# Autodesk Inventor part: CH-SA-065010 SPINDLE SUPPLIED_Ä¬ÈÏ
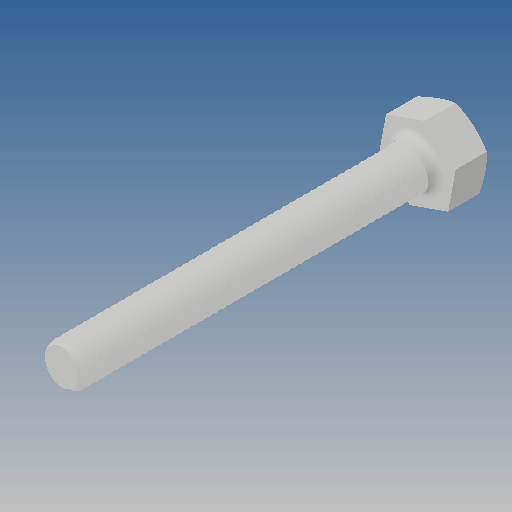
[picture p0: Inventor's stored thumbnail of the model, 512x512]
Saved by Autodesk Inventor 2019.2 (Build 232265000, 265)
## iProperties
Created: 2010-06
Part Number: CH-SA-065010 SPINDLE SUPPLIED_Ä¬ÈÏ
Material: Ogólny
Document SubType Name: Modeling
Designer: CADENGINEERING4
Density: 1 g/cm^3
Appearance: Domyślna
Author: CADENGINEERING4
Revision Number: ÈÎºÎ
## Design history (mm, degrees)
feature "NONE"
node "Bryła1"
